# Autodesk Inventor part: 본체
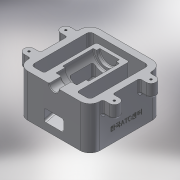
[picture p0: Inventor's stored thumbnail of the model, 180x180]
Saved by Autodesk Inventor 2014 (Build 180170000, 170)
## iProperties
Created: 2018-01
Part Number: 본체
Material: Aluminum 6061
Document SubType Name: Sheet Metal
Designer: user
Density: 2.71 g/cm^3
Appearance: Aluminum - Flat
Mass: 998.969 g
Surface Area: 834.538 cm^2
Volume: 368.623 cm^3
Sheet Metal Rule: Default
Author: user
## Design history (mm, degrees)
sketch "Sketch1"
  geometry: L1 (-40, 55)-(40, 55); L2 (55, 40)-(55, -40); L3 (40, -55)-(-40, -55); L4 (-55, -40)-(-55, 40); L5 (-55, 55)-(55, -55); L6 (55, 55)-(-55, -55); L7 (40, 45)-(-40, 45); L8 (-45, 40)-(-45, -40); L9 (-40, -45)-(40, -45); L10 (45, -40)-(45, 40); A1 r 15 centre (-40, 40) between (-40, 55) and (-55, 40); A2 r 15 centre (40, 40) between (55, 40) and (40, 55); A3 r 15 centre (40, -40) between (40, -55) and (55, -40); A4 r 15 centre (-40, -40) between (-55, -40) and (-40, -55); A5 r 5 centre (-40, 40) between (-40, 45) and (-45, 40); A6 r 5 centre (-40, -40) between (-45, -40) and (-40, -45); A7 r 5 centre (40, -40) between (40, -45) and (45, -40); A8 r 5 centre (40, 40) between (45, 40) and (40, 45); 1 further point
  constraints: 20 end point, 16 point on circle, 8 centre point, 8 point on line, 8 tangent, 4 parallel, 3 equal radius, 2 midpoint, 2 perpendicular, 1 horizontal, 7 other
  dimensions: "d0" = 110 distance of L5.end L6.end; "d1" = 110 distance of L6.start L5.end; "d2" = 15 radius of A1; "d3" = 10 distance between parallel lines of L1 L7
extrude "Extrusion1" new body sketch "Sketch1" distance "d4" = 65; taper "d5" = 0 deg
sketch "Sketch3"
  geometry: L1 (-40, -55)-(40, -55) reference; L2 (-55, 40)-(-55, -40) reference; L3 (-65, -35.5)-(-55, -35.5); L4 (-65, -20.5)-(-55, -20.5); A1 r 7.5 centre (-65, -28) between (-65, -20.5) and (-65, -35.5); 1 further point
  constraints: 4 end point, 2 point on circle, 2 point on line, 2 tangent, 1 centre point, 1 parallel, 1 perpendicular
  dimensions: "d6" = 15 diameter of A1; "d7" = 27 distance from line of L1 A1.centre; "d8" = 10 distance from line of L2 A1.centre
extrude "Extrusion2" join sketch "Sketch3" distance "d9" = 20; taper "d10" = 0 deg
pattern_linear "Rectangular Pattern1" dims "d13" = 56
mirror "Mirror1"
hole "Hole1" diameter "d16" = 3.242; stored, may be unused: countersink angle "d20" = 90 deg, drill point angle "d22" = 118 deg; dims "d14" = 10, "d15" = 10, "d17" = 9, "d18" = 4, "d19" = 2, "d21" = 11
pattern_linear "Rectangular Pattern2" dims "d25" = 56
sketch "Sketch4"
  geometry: L1 (40, -45)-(-40, -45) reference; L2 (-25, -45)-(25, -45); L3 (25, -45)-(25, 35); L4 (25, 35)-(-25, 35); L5 (-25, 35)-(-25, -45); L6 (0, 0)-(0, -45); L7 (40, 55)-(-40, 55) reference
  constraints: 10 end point, 2 parallel, 1 horizontal, 1 midpoint, 1 perpendicular, 1 point on line, 1 vertical
  dimensions: "d29" = 50 distance of L3.end L4.end; "d30" = 20 distance between parallel lines of L7 L4
extrude "Extrusion3" join sketch "Sketch4" distance "d31" = 65; taper "d32" = 0 deg
sketch "Sketch5"
  geometry: L1 (-40, -55)-(40, -55) reference; L2 (0, -55)-(0, 30); L3 (0, 30)-(-14, 30); L4 (-15, 29)-(-15, 25); L5 (-15, 25)-(-19, 25); L6 (-20, 24)-(-20, -21); L7 (-19, -22)-(-16, -22); L8 (-16, -22)-(-16, -35); L9 (-15, -36)-(-7.5, -36); L10 (-7.5, -36)-(-7.5, -55); L11 (0, -55)-(-7.5, -55); A1 r 1 centre (-14, 29) between (-14, 30) and (-15, 29); A2 r 1 centre (-19, 24) between (-19, 25) and (-20, 24); A3 r 1 centre (-19, -21) between (-20, -21) and (-19, -22); A4 r 1 centre (-15, -35) between (-16, -35) and (-15, -36); 1 further point
  constraints: 20 end point, 8 point on circle, 8 tangent, 6 parallel, 4 centre point, 4 perpendicular, 3 equal radius, 1 midpoint, 1 point on line
  dimensions: "d33" = 30 diameter of L4 L2; "d34" = 40 diameter of L6 L2; "d35" = 32 diameter of L8 L2; "d36" = 15 diameter of L10 L2; "d37" = 19 distance between parallel lines of L1 L9; "d38" = 14 distance between parallel lines of L7 L9; "d39" = 47 distance between parallel lines of L5 L7; "d40" = 5 distance between parallel lines of L3 L5; "d41" = 1 radius of A1
revolve "Revolution1" sketch "Sketch5" stored, may be unused: angle "d42" = 90 deg
chamfer "Chamfer1" distance "d43" = 1; stored, may be unused: second distance "d44" = 2, angle "d45" = 45 deg
sketch "Sketch6"
  geometry: L1 (0, 55)-(65, 55) reference; L2 (0, 45)-(0, -35) reference; L3 (0, 40)-(0, 55) reference; L4 (65, -35)-(0, -35) reference; L5 (6.262, 45)-(0, 45); L6 (9.16, 42.776)-(30, -35); A1 r 3 centre (6.262, 42) between (9.16, 42.776) and (6.262, 45); 1 further point
  constraints: 4 end point, 2 point on circle, 2 point on line, 2 tangent, 1 centre point, 1 perpendicular
  dimensions: "d46" = 30 distance from line of L2 L6.end; "d47" = 10 distance between parallel lines of L1 L5; "d49" = 105 deg angle of L5 L6; "d50" = 3 radius of A1
extrude "Extrusion4" cut sketch "Sketch6" stored distance "d51" = 65; taper "d52" = 0 deg
sketch "Sketch7"
  geometry: L1 (30, -35)-(9.16, 42.776) reference; L2 (0, 55)-(65, 55) reference; L3 (30.561, -17.776)-(11.061, 55); L4 (45, -24)-(45, 21) reference; L5 (45, -20)-(33.459, -20); L6 (65, -25)-(46, -25) reference; L7 (29.061, 55)-(38.647, 19.224); L8 (41.545, 17)-(45, 17); L9 (65, 22)-(46, 22) reference; L10 (45, 17)-(55, 17); L11 (55, 17)-(55, -20); L12 (55, -20)-(45, -20); A1 r 3 centre (41.545, 20) between (38.647, 19.224) and (41.545, 17); A2 r 3 centre (33.459, -17) between (30.561, -17.776) and (33.459, -20); 1 further point
  constraints: 14 end point, 4 parallel, 4 point on circle, 4 point on line, 4 tangent, 3 perpendicular, 2 centre point, 1 equal radius
  dimensions: "d53" = 5 distance between parallel lines of L1 L3; "d54" = 5 distance between parallel lines of L6 L5; "d55" = 18 distance of L3.end L7.start; "d56" = 5 distance between parallel lines of L9 L8; "d57" = 3 radius of A1; "d60" = 10 distance between parallel lines of L4 L11
extrude "Extrusion6" cut sketch "Sketch7" stored distance "d61" = 30; taper "d62" = 0 deg
sketch "Sketch8"
  geometry: L1 (0, 0)-(80, 0) reference; L2 (-15, 0)-(-15, 65) reference; 2 further points
  constraints: 1 other
  dimensions: "d63" = 20 distance from line of L1 point (40, 20); "d64" = 55 distance from line of L2 point (40, 20)
emboss "Emboss1" sketch "Sketch8" dims "d0" = 110, "d1" = 110, "d2" = 15, "d3" = 10, "d65" = 0.5, "d66" = 0
fillet "Fillet1" dims "d67" = 3
fillet "Fillet2" dims "d68" = 3
fillet "Fillet3" dims "d69" = 3
fillet "Fillet4" dims "d70" = 3
chamfer "Chamfer2" distance "d71" = 1; stored, may be unused: second distance "d72" = 2, angle "d73" = 45 deg
body "Solid1"
other parameters: "Thickness" = 0.5, "KFactor" = 4.4, "BendRadius" = 0.5 (= Thickness), "BendReliefWidth" = 0.5 (= Thickness), "BendReliefDepth" = 0.25 (= 0.5 x Thickness), "CornerReliefSize" = 2 (= 4 x Thickness), "SeamGap" = 0.01, "MinimumRemnant" = 1 (= 2 x Thickness), "TransitionRadius" = 0.5 (= BendRadius), "JacobiRadiusSize" = 0.5 (= Thickness), "GapSize" = 0.5 (= Thickness)
